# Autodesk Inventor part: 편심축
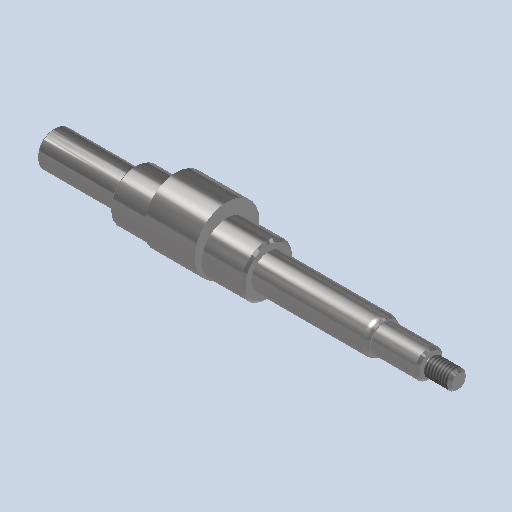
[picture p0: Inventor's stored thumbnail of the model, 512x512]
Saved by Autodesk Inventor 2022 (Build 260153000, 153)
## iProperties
Created: 2015-09
Part Number: 편심축
Material: 강철, 연강
Document SubType Name: Modeling
Designer: mduedu
Density: 1 g/cm^3
Appearance: 반광택
Author: mduedu
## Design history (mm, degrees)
sketch "스케치1"
  geometry: L1 (-87.5, 0)-(87.5, 0); L2 (-87.5, 0)-(-87.5, 7.5); L3 (-87.5, 7.5)-(-52.5, 7.5); L4 (-52.5, 7.5)-(-52.5, 11); L5 (-52.5, 11)-(5.5, 11); L6 (5.5, 11)-(5.5, 7.5); L7 (5.5, 7.5)-(53.855, 7.5); L8 (55.5, 6.55)-(55.5, 6); L9 (55.5, 6)-(75.5, 6); L10 (75.5, 6)-(75.5, 3); L11 (75.5, 3)-(76.5, 3); L12 (76.5, 3)-(76.5, 4); L13 (76.5, 4)-(87.5, 4); L14 (87.5, 4)-(87.5, 0); L15 (55.5, 6.55)-(53.855, 7.5); 2 further points
  constraints: 30 end point, 10 parallel, 2 perpendicular, 1 coincident, 1 collinear, 1 horizontal, 1 midpoint
  dimensions: "d0" = 35 distance of L2.end L3.end; "d2" = 58 distance of L4.end L5.end; "d4" = 175 distance of L1.start L1.end; "d5" = 20 distance of L8.end L9.end; "d6" = 1 distance of L10.end L11.end; "d7" = 8 diameter of L13 L1; "d8" = 6 diameter of L11 L1; "d9" = 12 diameter of L9 L1; "d10" = 15 diameter of L7 L1; "d11" = 22 diameter of L5 L1; "d12" = 15 diameter of L3 L1; "d40" = 13.1 diameter of L8.start L1; "d41" = 30 deg angle of L7 L15; "d43" = 50 distance between parallel lines of L8 L6
revolve "회전1" sketch "스케치1" stored, may be unused: angle "d13" = 90 deg
node "작업 평면1"
sketch "스케치3"
  geometry: C1 r 11 at (0, 0) reference; C2 r 14 at (0, 3); 1 further point
  constraints: 1 centre point, 1 tangent, 1 vertical alignment
  dimensions: "d19" = 28 diameter of C2
extrude "돌출1" join sketch "스케치3" stored distance "d21" = 22; taper "d22" = 0 deg
node "작업 평면2"
sketch "스케치4"
  geometry: L1 (10, 6.55)-(10, -6.55) reference; L2 (-10, 6)-(-10, -6) reference; L3 (10, 0)-(-10, 0); L4 (-5, -2)-(3, -2); L5 (3, 2)-(-5, 2); A1 r 2 centre (3, 0) between (3, -2) and (3, 2); A2 r 2 centre (-5, 0) between (-5, 2) and (-5, -2); 1 further point
  constraints: 6 end point, 4 point on circle, 4 tangent, 2 centre point, 2 midpoint, 2 parallel, 1 point on line
  dimensions: "d23" = 4 distance between parallel lines of L5 L4; "d25" = 12 dimension on A2 A1; "d26" = 3 distance edge to line of A2 L2
extrude "돌출2" cut sketch "스케치4" distance "d27" = 2.5; taper "d28" = 0 deg
chamfer "모따기1" distance "d29" = 1; stored, may be unused: second distance "d30" = 2, angle "d31" = 45 deg
feature "스레드1" dims "d32" = 10, "d33" = 0
chamfer "모따기2" distance "d34" = 1; stored, may be unused: second distance "d35" = 2, angle "d36" = 45 deg
chamfer "모따기3" distance "d37" = 1; stored, may be unused: second distance "d38" = 2, angle "d39" = 45 deg
fillet "모깎기1" dims "d42" = 4
node "솔리드1"
